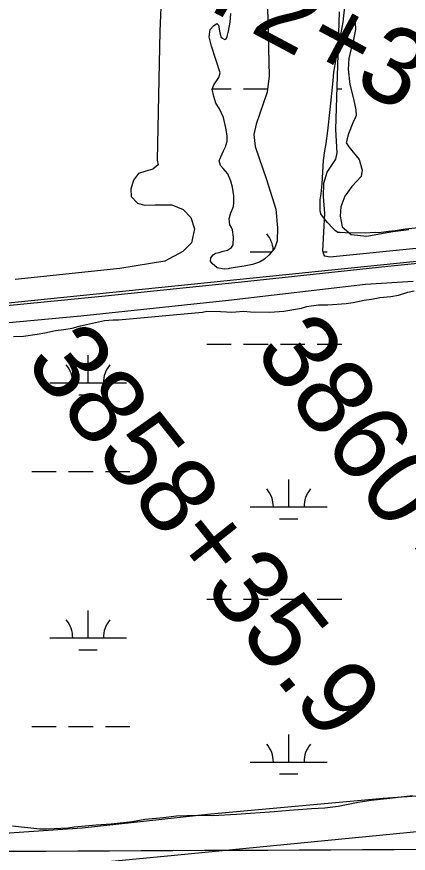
# Model space of a CAD drawing. Extents: x 3445503 to 3483459, y 540493 to 566012.
# Drawn here: x 3455146 to 3455656, y 551970 to 553061 of the extents above; entities that cross this region are included whole.
import ezdxf

# ---------------------------------------------------------------- set-up
doc = ezdxf.new("R2010")
doc.units = 0
for name, color, linetype in [('V-GRID-MAJR', 7, 'Continuous'), ('V-RAIL-TRAK', 7, 'Continuous'), ('V-ROAD-CNTR', 7, 'Continuous'), ('V-SITE-VEGE', 7, 'Continuous'), ('V-SURV-IDEN', 7, 'Continuous'), ('V-WETL-SWMP', 7, 'Continuous')]:
    doc.layers.add(name, color=color, linetype=linetype)

msp = doc.modelspace()

# ---------------------------------------------------------------- linework, layer by layer
at = {"layer": 'V-GRID-MAJR'}
msp.add_spline([(3449621.526, 551946.219), (3454896.117, 551971.152), (3460170.705, 551996.853), (3465445.288, 552023.321), (3470719.8680000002, 552050.556), (3475994.444, 552078.558), (3481269.015, 552107.327), (3481269.0160000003, 552107.327)], degree=3, dxfattribs=at)
at = {"layer": 'V-RAIL-TRAK'}
msp.add_lwpolyline([(3455824.363, 552754.742), (3455629.733, 552735.233), (3455447.365, 552715.509), (3455261.136, 552696.497), (3455079.769, 552678.694), (3454899.066, 552661.845), (3454811.811, 552655.304)], dxfattribs=at)
at = {"layer": 'V-ROAD-CNTR'}
for points in [[(3462631.285699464, 553461.3070510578), (3461591.307779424, 553353.2252672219), (3460578.969804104, 553249.1104754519), (3460106.5807488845, 553200.928571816), (3459452.7400565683, 553132.438708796), (3458819.349323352, 553067.889837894), (3458004.174953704, 552983.141007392), (3457426.1801096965, 552925.1971232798), (3456974.920012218, 552876.8662199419), (3456477.6580067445, 552824.1753253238), (3455722.188517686, 552747.3734789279), (3455105.053751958, 552684.0966054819)], [(3456854.165253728, 552249.4804747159), (3456421.5741189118, 552143.80368607), (3455983.337995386, 552038.8818959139), (3455725.612510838, 552003.37896692), (3455338.2512855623, 551965.665042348), (3455008.94294418, 551934.2321052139), (3454728.182505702, 551906.5051606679)]]:
    msp.add_lwpolyline(points, dxfattribs=at)
at = {"layer": 'V-SITE-VEGE'}
for points in [[(3455342.509, 553280.9230000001), (3455332.501, 553042.0480000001), (3455328.906, 552873.676), (3455330.1, 552867.825), (3455323.52, 552862.109), (3455314.409, 552859.678), (3455304.6380000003, 552856.61), (3455298.002, 552847.656), (3455294.561, 552836.054), (3455295.039, 552826.328), (3455303.311, 552817.761), (3455312.332, 552815.013), (3455326.59, 552815.41), (3455347.975, 552815.685), (3455362.768, 552809.596), (3455372.949, 552799.053), (3455377.87, 552784.068), (3455373.665, 552766), (3455362.453, 552754.535), (3455338.911, 552741.991), (3455280.443, 552732.648), (3455144.146, 552718.1900000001)], [(3455673.757, 552786.138), (3455652.107, 552783.648), (3455638.972, 552781.731), (3455630.4560000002, 552780.803), (3455617.676, 552779.234), (3455613.429, 552779.302), (3455599.951, 552778.454), (3455574.1010000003, 552778.8640000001), (3455567.378, 552779.326), (3455564.543, 552779.3690000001), (3455561.3910000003, 552781.544), (3455557.904, 552785.143), (3455550.94, 552792.692), (3455547.119, 552797.357), (3455542.261, 552803.81), (3455541.264, 552808.076), (3455541.485, 552821.888), (3455542.677, 552830.017), (3455543.946, 552843.103), (3455545.847, 552873.537), (3455547.4590000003, 552885.911), (3455549.382, 552895.444), (3455551.415, 552912.059), (3455554.338, 552939.996), (3455558.469, 552977.128), (3455559.358, 552988.45), (3455562.116, 553006.118), (3455564.7970000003, 553018.828), (3455568.676, 553040.02), (3455571.373, 553053.791), (3455573.47, 553074.304)], [(3455141.918, 552643.667), (3455155.031, 552644.167), (3455172.429, 552646.725), (3455182.735, 552648.687), (3455196.595, 552651.654), (3455207.2430000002, 552652.903), (3455218.251, 552654.501), (3455229.281, 552657.868), (3455248.481, 552662.169), (3455260.208, 552664.462), (3455271.562, 552665.699), (3455278.644, 552665.587), (3455388.262, 552675.54), (3455393.953, 552676.865), (3455411.6580000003, 552676.584), (3455419.436, 552675.753), (3455426.52, 552675.64), (3455431.485, 552675.917), (3455441.417, 552676.822), (3455450.613, 552675.968), (3455475.756, 552675.569), (3455494.201, 552677.047), (3455517.288, 552680.932), (3455523.696, 552682.956), (3455539.318, 552685.188), (3455551.358, 552684.998), (3455575.119, 552686.747), (3455584.349, 552688.0160000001), (3455598.5670000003, 552690.98), (3455608.5100000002, 552692.594), (3455619.169, 552694.55), (3455633.716, 552696.09), (3455643.307, 552697.71), (3455655.769, 552701.761), (3455663.943, 552703.403)], [(3455661.647, 552044.566), (3455647.094, 552042.669), (3455632.191, 552041.135), (3455608.057, 552038.329), (3455591.0160000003, 552035.765), (3455564.723, 552030.868), (3455547.684, 552028.661), (3455529.957, 552027.524), (3455501.586, 552025.495), (3455481.366, 552023.688), (3455432.4250000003, 552020.215), (3455401.582, 552018.578), (3455381.038, 552018.902), (3455354.103, 552017.9130000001), (3455337.424, 552016.051), (3455312.944, 552013.606), (3455296.958, 552010.671), (3455269.2770000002, 552007.5700000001), (3455249.424, 552006.4670000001), (3455221.04, 552003.728), (3455212.519, 552002.446), (3455185.575, 552001.103), (3455176.0130000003, 552001.252), (3455140.65, 552005.002)]]:
    msp.add_lwpolyline(points, dxfattribs=at)
at = {"layer": 'V-WETL-SWMP'}
for p, q in [((3455400.581325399, 552966.6670302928), (3455425.5569378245, 552966.6670302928)), ((3455441.5569378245, 552966.6670302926), (3455472.985917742, 552966.6670302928)), ((3455563.613296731, 552966.6670302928), (3455569.5569378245, 552966.6670302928)), ((3455450.400937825, 552754.0630302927), (3455478.0008001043, 552754.0630302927)), ((3455545.1355529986, 552754.0630302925), (3455550.4009378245, 552754.0630302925)), ((3455393.5597786, 552633.9926471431), (3455425.5597749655, 552633.9926471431)), ((3455441.559773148, 552633.9926471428), (3455473.5597695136, 552633.9926471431)), ((3455489.5597676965, 552633.9926471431), (3455521.559764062, 552633.9926471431)), ((3455537.559762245, 552633.9926471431), (3455569.559758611, 552633.9926471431)), ((3455238.9678066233, 552583.2506518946), (3455238.9677991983, 552619.2506485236)), ((3455188.9678123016, 552583.2506518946), (3455288.9678009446, 552583.2506518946)), ((3455226.9678111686, 552567.8196533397), (3455250.967808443, 552567.8196533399)), ((3455165.559838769, 552467.818662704), (3455197.5598351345, 552467.818662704)), ((3455213.5598333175, 552467.8186627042), (3455245.559829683, 552467.818662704)), ((3455261.5598278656, 552467.8186627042), (3455293.559824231, 552467.818662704)), ((3455500.4038103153, 552421.3886670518), (3455500.4038028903, 552457.388663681)), ((3455450.4038159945, 552421.3886670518), (3455550.403804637, 552421.3886670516)), ((3455488.4038148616, 552405.9576684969), (3455512.4038121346, 552405.9576684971)), ((3455393.5598472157, 552301.3176782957), (3455425.559843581, 552301.3176782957)), ((3455441.559841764, 552301.3176782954), (3455473.5598381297, 552301.3176782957)), ((3455489.559836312, 552301.3176782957), (3455521.5598326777, 552301.3176782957)), ((3455537.559830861, 552301.3176782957), (3455569.5598272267, 552301.3176782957)), ((3455238.9678752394, 552250.5756830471), (3455238.967867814, 552286.575679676)), ((3455188.9678809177, 552250.5756830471), (3455288.9678695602, 552250.5756830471)), ((3455226.9678797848, 552235.1446844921), (3455250.9678770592, 552235.1446844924)), ((3455165.559907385, 552135.1436938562), (3455197.559903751, 552135.1436938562)), ((3455213.5599019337, 552135.1436938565), (3455245.559898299, 552135.1436938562)), ((3455261.5598964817, 552135.1436938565), (3455293.559892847, 552135.1436938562)), ((3455500.4038789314, 552088.713698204), (3455500.403871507, 552124.7136948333)), ((3455450.4038846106, 552088.713698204), (3455550.403873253, 552088.7136982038)), ((3455488.403883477, 552073.2826996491), (3455512.403880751, 552073.2826996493))]:
    msp.add_line(p, q, dxfattribs=at)
for points in [[(3455472.853, 553073.085), (3455474.848, 552983.813), (3455472.535, 552962.515)], [(3455415.238, 552755.297), (3455420.719, 552756.537), (3455425.946, 552759.998), (3455428.262, 552763.186), (3455428.437, 552773.193), (3455427.316, 552782.899), (3455426.0810000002, 552786.15), (3455423.555, 552789.4230000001), (3455422.722, 552797.187), (3455424.449, 552803.615), (3455428.492, 552813.231), (3455428.911, 552818.713), (3455428.74, 552827.434), (3455426.9960000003, 552838.443), (3455425.2, 552846.547), (3455421.168, 552855.981), (3455414.83, 552862.873), (3455411.67, 552866.803), (3455409.841, 552872.97), (3455412.19, 552878.095), (3455415.56, 552886.109), (3455417.91, 552891.234), (3455420.299, 552898.618), (3455420.089, 552905.08), (3455418.95, 552913.818), (3455415.671, 552929.3740000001), (3455410.058, 552940.774), (3455405.346, 552948.283), (3455402.9080000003, 552956.728), (3455400.494, 552966.465), (3455402.8510000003, 552971.9180000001), (3455409.482, 552981.497), (3455411.205, 552987.607), (3455399.856, 553022.384), (3455396.84, 553034.716), (3455397.973, 553044.068), (3455402.264, 553049.164), (3455406.8370000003, 553051.992), (3455408.742, 553050.02), (3455410.828, 553039.965), (3455412.336, 553033.799), (3455417.137, 553031.13), (3455419.092, 553032.0650000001), (3455420.441, 553035.273), (3455422.1750000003, 553042.029), (3455424.3170000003, 553053.625), (3455425.166, 553065.2440000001)], [(3455787.562, 552770.612), (3455554.234, 552747.133), (3455547.369, 552748.631), (3455546.0270000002, 552750.7220000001), (3455544.734, 552755.568), (3455547.657, 552804.444), (3455545.9760000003, 552826.524), (3455546.278, 552843.747), (3455550.664, 552858.1410000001), (3455561.988, 552875.171), (3455563.511, 552883.4130000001), (3455561.975, 552913.761), (3455566.731, 553067.348)], [(3455586.6240000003, 553062.176), (3455587.688, 553044.24), (3455585.429, 553033.254), (3455584.643, 553027.755), (3455581.7430000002, 553019.537), (3455578.758, 553006.496), (3455577.828, 552992.73), (3455580.234, 552972.704), (3455584.731, 552954.019), (3455587.9220000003, 552939.492), (3455588.478, 552931.903), (3455587.052, 552929.171), (3455584.176, 552922.33), (3455578.412, 552907.96), (3455575.451, 552896.297), (3455578.811, 552891.415), (3455592.299, 552874.64), (3455596.1920000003, 552860.79), (3455594.669, 552852.547), (3455582.7290000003, 552839.6630000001), (3455573.544, 552826.731), (3455568.481, 552813.037), (3455567.575, 552800.649), (3455570.089, 552786.823), (3455581.631, 552776.974), (3455602.262, 552774.545), (3455618.856, 552777.7), (3455636.1380000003, 552780.843), (3455656.853, 552783.237)], [(3455472.535, 552962.515), (3455458.224, 552920.733), (3455455.078, 552907.209), (3455456.7460000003, 552891.66), (3455471.514, 552848.723), (3455483.447, 552810.039), (3455485.932, 552785.746), (3455485.309, 552768.621), (3455482.565, 552759.616), (3455474.967, 552750.372), (3455469.0470000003, 552744.656), (3455462.186, 552740.573), (3455453.4080000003, 552737.817), (3455442.373, 552735.4230000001), (3455430.703, 552733.687), (3455422.923, 552732.53), (3455421.619, 552731.906), (3455416.4420000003, 552731.674), (3455407.096, 552733.454), (3455400.728, 552739.062), (3455398.5160000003, 552742.01), (3455398.919, 552746.53), (3455401.896, 552750.357), (3455404.844, 552752.569), (3455409.7090000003, 552753.454), (3455415.238, 552755.297)], [(3455065.365, 552655.491), (3455229.646, 552670.697), (3455421.787, 552691.228), (3455600.3710000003, 552711.995), (3455662.755, 552716.0700000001)], [(3455779.157, 552052.189), (3455623.4, 552041.036), (3455398.739, 552020.761), (3455231.237, 552002.39), (3455091.969, 551992.885)]]:
    msp.add_lwpolyline(points, dxfattribs=at)
for centre, radius, start, end in [((3455445.1580017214, 552754.5378334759), 35.24628790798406, 3.828906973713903, 40.77183827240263), ((3455183.724876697, 552583.7254550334), 35.24628790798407, 359.22817992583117, 40.771838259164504), ((3455294.2107363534, 552583.7254550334), 35.24628790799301, 139.22817695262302, 180.77183528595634), ((3455445.1608803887, 552421.8634701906), 35.24628790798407, 359.22817992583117, 40.771838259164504), ((3455555.6467400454, 552421.8634701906), 35.24628790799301, 139.22817695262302, 180.77183528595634), ((3455183.724945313, 552251.0504861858), 35.24628790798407, 359.22817992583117, 40.771838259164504), ((3455294.2108049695, 552251.0504861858), 35.24628790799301, 139.22817695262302, 180.77183528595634), ((3455445.1609490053, 552089.1885013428), 35.24628790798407, 359.22817992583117, 40.771838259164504), ((3455555.6468086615, 552089.1885013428), 35.24628790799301, 139.22817695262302, 180.77183528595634)]:
    msp.add_arc(centre, radius, start, end, dxfattribs=at)

# ---------------------------------------------------------------- texts
at = {"layer": 'V-SURV-IDEN'}
for s, height, rotation, p in [('3872+36.0', 100.00000000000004, 331.86444204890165, (3455251.3549901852, 553147.571444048)), ('3860+96.7', 100, 307.25597540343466, (3455453.779539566, 552623.6577704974)), ('3858+35.9', 100.00000000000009, 308.49857318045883, (3455154.8594360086, 552609.3223223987))]:
    msp.add_text(s, height=height, rotation=rotation, dxfattribs=at).set_placement(p)

doc.saveas('drawing.dxf')
